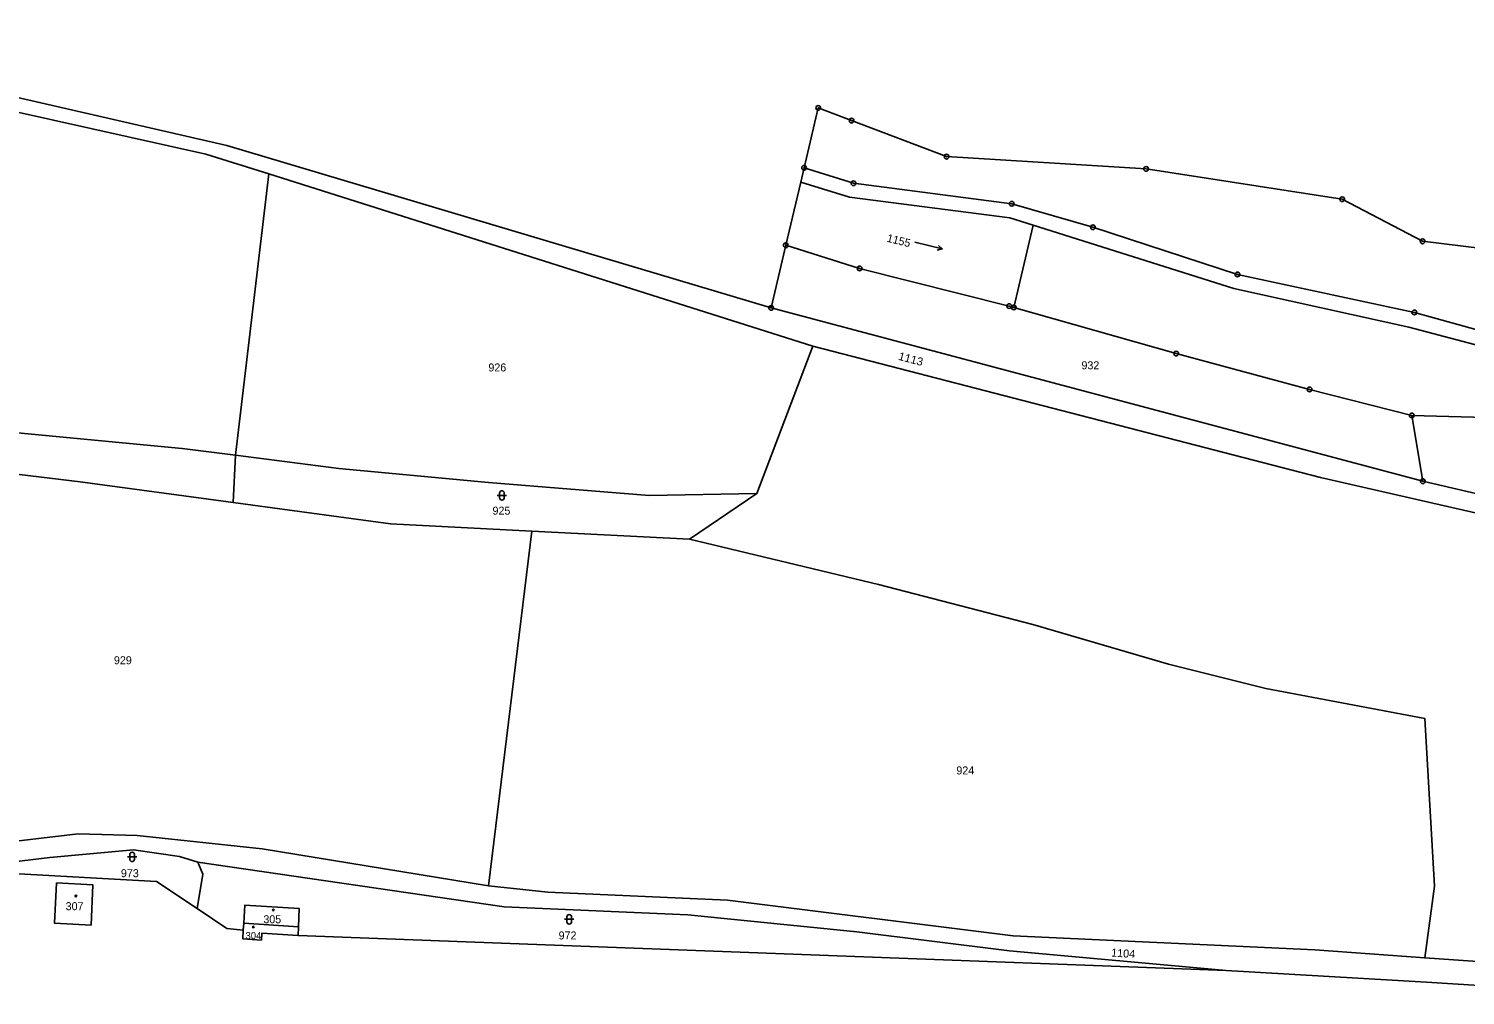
# Model space of a CAD drawing. Extents: x -758887 to -754328, y -1031688 to -1029144.
# Drawn here: x -756838.8 to -756533.6, y -1029651.7 to -1029446.2 of the extents above; entities that cross this region are included whole.
import ezdxf
from ezdxf.enums import TextEntityAlignment as Align

# ---------------------------------------------------------------- set-up
doc = ezdxf.new("R2010")
doc.units = 0
doc.header["$LTSCALE"] = 0.68
for name, color, linetype, lineweight in [('1', 7, 'Continuous', 25), ('3', 7, 'Continuous', 25), ('5', 7, 'Continuous', 25), ('8', 7, 'Continuous', 25)]:
    doc.layers.add(name, color=color, linetype=linetype, lineweight=lineweight)
doc.layers.add('2', color=7, linetype='Continuous')

msp = doc.modelspace()

# ---------------------------------------------------------------- linework, layer by layer
at = {"layer": '1'}
for p, q in [((-756674.05, -1029475.76), (-756671.05, -1029463.04)), ((-756674.77, -1029478.8), (-756674.05, -1029475.76)), ((-756677.94, -1029492.24), (-756674.77, -1029478.8)), ((-756625.38, -1029487.97), (-756629.5, -1029505.44)), ((-756681.08, -1029505.55), (-756542.61, -1029542.38)), ((-756793.11, -1029636.38), (-756793.2, -1029637.86)), ((-756781.52, -1029638.94), (-756584.4, -1029646.39))]:
    msp.add_line(p, q, dxfattribs=at)
for points in [[(-756946.71, -1029446.19), (-756922.99, -1029448.49), (-756878.16, -1029453.27), (-756864.7, -1029455.42), (-756796.69, -1029471.04), (-756681.08, -1029505.55), (-756677.94, -1029492.24)], [(-756787.78, -1029477.02), (-756801.18, -1029472.88), (-756865.96, -1029458.4), (-756927.21, -1029451.82), (-756933.02, -1029518.73)], [(-756671.05, -1029463.04), (-756663.96, -1029465.73), (-756643.78, -1029473.39), (-756601.39, -1029476.01), (-756559.73, -1029482.45), (-756542.65, -1029491.39), (-756512.15, -1029495.13), (-756511.48, -1029492.14)], [(-756672.22, -1029513.71), (-756787.78, -1029477.02), (-756794.86, -1029536.88)], [(-756674.05, -1029475.76), (-756663.58, -1029479.03), (-756629.93, -1029483.41), (-756612.69, -1029488.39), (-756582, -1029498.42), (-756544.4, -1029506.52), (-756500.42, -1029518.7), (-756408.95, -1029537.54), (-756374.46, -1029543.74)], [(-756625.38, -1029487.97), (-756630.35, -1029486.41), (-756664.43, -1029482.02), (-756674.77, -1029478.8)], [(-756501.32, -1029521.34), (-756545.57, -1029509.67), (-756582.75, -1029501.39), (-756625.38, -1029487.97)], [(-756629.5, -1029505.44), (-756630.47, -1029505.17), (-756662.25, -1029497.14), (-756677.94, -1029492.24)], [(-756544.94, -1029528.41), (-756566.65, -1029522.88), (-756594.99, -1029515.24), (-756629.5, -1029505.44)], [(-756672.22, -1029513.71), (-756684.08, -1029545.03), (-756698.41, -1029554.69)], [(-756444.95, -1029578.02), (-756457.6, -1029573.75), (-756513.5, -1029553.2), (-756564.32, -1029541.57), (-756672.22, -1029513.71)], [(-756794.86, -1029536.88), (-756806.19, -1029535.43), (-756872.51, -1029529.13), (-756904.96, -1029523.87), (-756933.02, -1029518.73), (-756933.9, -1029528.11)], [(-756795.34, -1029546.92), (-756827.83, -1029542.53), (-756860.19, -1029538.61), (-756893.25, -1029534.07), (-756925.94, -1029529.16), (-756933.9, -1029528.11)], [(-756127.09, -1029626.45), (-756157.91, -1029616.74), (-756237.19, -1029597.03), (-756263.17, -1029588.75), (-756326.66, -1029573.51), (-756369.87, -1029561.59), (-756411.53, -1029550.38), (-756458.47, -1029538.99), (-756502.99, -1029529.52), (-756544.94, -1029528.41), (-756542.61, -1029542.38)], [(-756684.08, -1029545.03), (-756706.96, -1029545.42), (-756741.08, -1029542.69), (-756772.93, -1029539.69), (-756794.86, -1029536.88), (-756795.34, -1029546.92)], [(-756542.61, -1029542.38), (-756513.13, -1029549.25), (-756479.83, -1029558.51), (-756423.63, -1029580.06), (-756373.3, -1029593.1), (-756337.45, -1029605.31), (-756309.67, -1029613.74), (-756270.97, -1029623.94), (-756250.01, -1029629.16), (-756234.28, -1029629.08)], [(-756795.34, -1029546.92), (-756761.94, -1029551.46), (-756731.87, -1029552.99)], [(-756698.41, -1029554.69), (-756731.87, -1029552.99), (-756741.1, -1029628.39)], [(-756698.41, -1029554.69), (-756658.23, -1029564.32), (-756625.45, -1029572.88), (-756596.62, -1029581.32), (-756575.93, -1029586.45), (-756542.15, -1029592.86), (-756540.12, -1029628.5), (-756542.18, -1029643.73), (-756454.64, -1029649.83)], [(-756853.46, -1029616.12), (-756847.58, -1029619.6), (-756828.29, -1029617.39), (-756815.78, -1029617.73), (-756789.21, -1029620.52), (-756741.1, -1029628.39)], [(-756802.89, -1029623.39), (-756806.75, -1029622.2), (-756816.51, -1029620.79), (-756834.29, -1029622.37), (-756841.98, -1029623.32), (-756844.75, -1029625.66)], [(-756802.89, -1029623.39), (-756801.83, -1029625.9), (-756803, -1029633.25)], [(-756584.4, -1029646.39), (-756630.42, -1029642.26), (-756662.83, -1029638.21), (-756698.77, -1029634.58), (-756737.76, -1029632.85), (-756802.89, -1029623.39)], [(-756844.75, -1029625.66), (-756811.62, -1029627.46), (-756803, -1029633.25)], [(-756741.1, -1029628.39), (-756728.5, -1029629.79), (-756690.33, -1029631.48), (-756629.61, -1029639.06), (-756565.51, -1029642.01), (-756542.18, -1029643.73)], [(-756803, -1029633.25), (-756796.71, -1029637.48), (-756793.2, -1029637.86)], [(-756781.45, -1029637.15), (-756781.3, -1029633.24), (-756792.89, -1029632.54), (-756793.11, -1029636.38)], [(-756793.2, -1029637.86), (-756793.3, -1029639.69), (-756789.35, -1029639.95), (-756789.26, -1029638.45), (-756781.52, -1029638.94), (-756781.45, -1029637.15), (-756793.11, -1029636.38)], [(-756384.04, -1029658.86), (-756541.79, -1029648.89), (-756584.4, -1029646.39)]]:
    msp.add_lwpolyline(points, dxfattribs=at)
msp.add_lwpolyline([(-756832.9, -1029627.8), (-756833.33, -1029636.32), (-756825.53, -1029636.76), (-756825.15, -1029628.21)], close=True, dxfattribs=at)
at = {"layer": '3'}
for p, q in [((-756644.705, -1029492.988), (-756645.774, -1029493.238)), ((-756739.251, -1029545.401), (-756737.249, -1029545.401)), ((-756738.751, -1029544.901), (-756738.751, -1029545.902)), ((-756737.749, -1029545.902), (-756737.749, -1029544.901)), ((-756817.831, -1029622.261), (-756815.829, -1029622.261)), ((-756817.331, -1029621.761), (-756817.331, -1029622.762)), ((-756816.329, -1029622.762), (-756816.329, -1029621.761)), ((-756724.961, -1029635.531), (-756722.959, -1029635.531)), ((-756724.461, -1029635.031), (-756724.461, -1029636.032)), ((-756723.459, -1029636.032), (-756723.459, -1029635.031))]:
    msp.add_line(p, q, dxfattribs=at)
msp.add_lwpolyline([(-756650.526, -1029491.537), (-756644.705, -1029492.988), (-756645.531, -1029492.265)], dxfattribs=at)
for centre, start, end in [((-756738.25, -1029544.9009), 0, 180), ((-756738.25, -1029545.9009), 180, 359.98789), ((-756816.83, -1029621.7609), 0, 180), ((-756816.83, -1029622.7609), 180, 359.98789), ((-756723.96, -1029635.0309), 0, 180), ((-756723.96, -1029636.0309), 180, 359.98789)]:
    msp.add_arc(centre, 0.5, start, end, dxfattribs=at)
at = {"layer": '5'}
for centre in [(-756828.7768, -1029630.5892), (-756786.8268, -1029633.5592), (-756791.0568, -1029637.1492)]:
    msp.add_circle(centre, 0.175, dxfattribs=at)
at = {"layer": '8'}
for centre, radius in [((-756671.05, -1029463.0399), 0.5), ((-756671.05, -1029463.0399), 0.0303), ((-756663.96, -1029465.7299), 0.5), ((-756663.96, -1029465.7299), 0.0303), ((-756643.78, -1029473.3899), 0.5), ((-756643.78, -1029473.3899), 0.0303), ((-756674.05, -1029475.7599), 0.5), ((-756674.05, -1029475.7599), 0.0303), ((-756601.39, -1029476.0099), 0.5), ((-756601.39, -1029476.0099), 0.0303), ((-756663.58, -1029479.0299), 0.5), ((-756663.58, -1029479.0299), 0.0303), ((-756629.93, -1029483.4099), 0.5), ((-756629.93, -1029483.4099), 0.0303), ((-756559.73, -1029482.4499), 0.5), ((-756559.73, -1029482.4499), 0.0303), ((-756612.69, -1029488.3899), 0.5), ((-756612.69, -1029488.3899), 0.0303), ((-756677.94, -1029492.2399), 0.5), ((-756677.94, -1029492.2399), 0.0303), ((-756542.65, -1029491.3899), 0.5), ((-756542.65, -1029491.3899), 0.0303), ((-756662.25, -1029497.1399), 0.5), ((-756662.25, -1029497.1399), 0.0303), ((-756582, -1029498.4199), 0.5), ((-756582, -1029498.4199), 0.0303), ((-756681.08, -1029505.5499), 0.5), ((-756681.08, -1029505.5499), 0.0303), ((-756630.47, -1029505.1699), 0.5), ((-756630.47, -1029505.1699), 0.0303), ((-756629.5, -1029505.4399), 0.5), ((-756629.5, -1029505.4399), 0.0303), ((-756544.4, -1029506.5199), 0.5), ((-756544.4, -1029506.5199), 0.0303), ((-756594.99, -1029515.2399), 0.5), ((-756594.99, -1029515.2399), 0.0303), ((-756566.65, -1029522.8799), 0.5), ((-756566.65, -1029522.8799), 0.0303), ((-756544.94, -1029528.4099), 0.5), ((-756544.94, -1029528.4099), 0.0303), ((-756542.61, -1029542.3799), 0.5), ((-756542.61, -1029542.3799), 0.0303)]:
    msp.add_circle(centre, radius, dxfattribs=at)

# ---------------------------------------------------------------- texts
at = {"layer": '2'}
for s, rotation, p in [('1155', 346, (-756654.1356, -1029492.0486)), ('1104', 356, (-756606.3183, -1029643.6057))]:
    msp.add_text(s, height=1.7, rotation=rotation, dxfattribs=at).set_placement(p, align=Align.CENTER)
for s, height, p in [('926', 1.7, (-756739.229, -1029519.056)), ('932', 1.7, (-756613.229, -1029518.596)), ('925', 1.7, (-756738.359, -1029549.506)), ('929', 1.7, (-756818.789, -1029581.306)), ('924', 1.7, (-756639.809, -1029604.726)), ('973', 1.7, (-756817.309, -1029626.576)), ('307', 1.7, (-756829.049, -1029633.586)), ('305', 1.7, (-756787.049, -1029636.366)), ('304', 1.5, (-756791.049, -1029639.739)), ('972', 1.7, (-756724.309, -1029639.806))]:
    msp.add_text(s, height=height, dxfattribs=at).set_placement(p, align=Align.CENTER)
at = {"layer": '2', "width": 1.05}
msp.add_text('1113', height=1.7, rotation=345, dxfattribs=at).set_placement((-756651.59, -1029517.2271), align=Align.CENTER)

doc.saveas('drawing.dxf')
